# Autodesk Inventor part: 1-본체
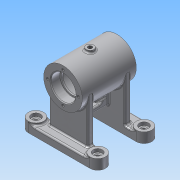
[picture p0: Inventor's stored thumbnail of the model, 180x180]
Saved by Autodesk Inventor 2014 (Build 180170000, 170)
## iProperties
Created: 2015-11
Part Number: 1-본체
Material: 알루미늄 6061
Document SubType Name: Modeling
Designer: 03
Mass: 359.022 g
Surface Area: 459.449 cm^2
Volume: 132.48 cm^3
Density: 2.71 g/cm^3
Appearance: 알루미늄 - 평지
Author: 03
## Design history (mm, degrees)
sketch "스케치1"
  geometry: L1 (-40, 40)-(40, 40); L2 (40, 40)-(40, 20); L3 (40, 20)-(-40, 20); L4 (-40, 20)-(-40, 40); L5 (0, 0)-(-40, 0); L6 (-40, -40)-(40, -40); L7 (40, -40)-(40, -20); L8 (40, -20)-(-40, -20); L9 (-40, -20)-(-40, -40); A1 r 10 centre (40, 30) between (40, 20) and (40, 40); A2 r 10 centre (-40, 30) between (-40, 40) and (-40, 20); A3 r 10 centre (40, -30) between (40, -40) and (40, -20); A4 r 10 centre (-40, -30) between (-40, -20) and (-40, -40); 2 further points
  constraints: 18 end point, 8 point on circle, 7 symmetric about line, 4 centre point, 3 midpoint, 2 parallel, 2 perpendicular, 1 horizontal, 1 vertical alignment, 2 other
  dimensions: "d0" = 20 distance of L1.end L2.end; "d1" = 80 distance of L1.start L1.end; "d2" = 40 distance from line of L5.start L1; "d3" = 40 distance of L5.start L5.end
extrude "돌출1" new body sketch "스케치1" distance "d4" = 10; taper "d5" = 0 deg
sketch "스케치2"
  geometry: L1 (40, 40)-(-40, 40) reference; L2 (-40, 20)-(40, 20) reference; A1 r 10 centre (40, -30) between (40, -40) and (40, -20) reference; A2 r 10 centre (-40, -30) between (-40, -20) and (-40, -40) reference; A3 r 10 centre (-40, 30) between (-40, 40) and (-40, 20) reference; A4 r 10 centre (40, 30) between (40, 20) and (40, 40) reference; 5 further points
  constraints: 4 coincident, 4 vertical alignment, 8 other
extrude "돌출2" join sketch "스케치2" distance "d6" = 3; taper "d7" = 0 deg
hole "구멍1" diameter "d10" = 6; stored, may be unused: countersink angle "d14" = 90 deg, drill point angle "d16" = 118 deg; dims "d8" = 10, "d9" = 10, "d11" = 6, "d12" = 12, "d13" = 4, "d15" = 8
hole "구멍2" diameter "d19" = 6; stored, may be unused: countersink angle "d23" = 90 deg, drill point angle "d25" = 118 deg; dims "d17" = 10, "d18" = 10, "d20" = 6, "d21" = 12, "d22" = 4, "d24" = 8
hole "구멍3" diameter "d28" = 6; stored, may be unused: countersink angle "d32" = 90 deg, drill point angle "d34" = 118 deg; dims "d26" = 10, "d27" = 10, "d29" = 6, "d30" = 12, "d31" = 4, "d33" = 8
hole "구멍4" diameter "d37" = 6; stored, may be unused: countersink angle "d41" = 90 deg, drill point angle "d43" = 118 deg; dims "d35" = 10, "d36" = 10, "d38" = 6, "d39" = 12, "d40" = 4, "d42" = 8
sketch "스케치5"
  geometry: L1 (-35, 68)-(35, 68); L2 (-35, 93)-(-35, 85); L3 (-34, 84)-(-23.3, 84); L4 (-23, 83.7)-(-23, 82); L5 (-23, 82)-(-21, 82); L6 (-21, 82)-(-21, 86); L7 (-18, 89)-(18, 89); L8 (21, 86)-(21, 82); L9 (21, 82)-(23, 82); L10 (23, 82)-(23, 83.7); L11 (23.3, 84)-(34, 84); L12 (35, 85)-(35, 93); L13 (35, 93)-(-35, 93); L14 (-35, 85)-(-34, 84); L15 (34, 84)-(35, 85); A1 r 0.3 centre (-23.3, 83.7) between (-23, 83.7) and (-23.3, 84); A2 r 0.3 centre (23.3, 83.7) between (23.3, 84) and (23, 83.7); A3 r 3 centre (18, 86) between (21, 86) and (18, 89); A4 r 3 centre (-18, 86) between (-18, 89) and (-21, 86); 9 further points
  constraints: 30 end point, 13 point on line, 9 parallel, 8 point on circle, 8 tangent, 4 centre point, 2 collinear, 2 midpoint, 2 perpendicular, 2 vertical alignment, 1 equal radius, 1 horizontal
  dimensions: "d66" = 68 vertical distance of point (0, 0) L1.end; "d67" = 32 diameter of L3 L1; "d68" = 28 diameter of L5 L1; "d69" = 28 diameter of L9 L1; "d70" = 32 diameter of L11 L1; "d71" = 42 diameter of L7 L1; "d72" = 42 distance of point (-21, 89) point (21, 89); "d73" = 12 distance of point (23, 84) point (35, 84); "d74" = 12 distance of point (-35, 84) point (-23, 84); "d75" = 70 distance of L12.end L2.start; "d76" = 50 diameter of L13 L1; "d78" = 0.3 radius of A1; "d79" = 0.3 radius of A2; "d80" = 3 radius of A3; "d81" = 1 distance of L2.end point (-35, 84); "d82" = 1 distance of L3.start point (-35, 84) (= d81); "d83" = 1 distance of L11.end point (35, 84) (= d81); "d84" = 1 distance of L12.start point (35, 84) (= d83)
revolve "회전2" sketch "스케치5" stored, may be unused: angle "d77" = 90 deg
sketch "스케치4"
  geometry: L1 (40, -20)-(-40, -20) reference; L2 (-40, 40)-(40, 40) reference; L3 (40, 20)-(-40, 20) reference; L4 (-25, -20)-(25, -20); L5 (25, -20)-(25, -28); L6 (25, -28)-(-25, -28); L7 (-25, -28)-(-25, -20); L8 (-25, 20)-(25, 20); L9 (25, 20)-(25, 28); L10 (25, 28)-(-25, 28); L11 (-25, 28)-(-25, 20); C1 r 3 at (40, 30) reference; C2 r 3 at (-40, 30) reference; A1 r 10 centre (40, 30) between (40, 20) and (40, 40) reference; A2 r 10 centre (-40, 30) between (-40, 40) and (-40, 20) reference; 3 further points
  constraints: 16 end point, 4 parallel, 2 horizontal, 2 midpoint, 2 perpendicular, 2 point on line, 2 vertical alignment
  dimensions: "d62" = 8 distance of L8.end L9.end; "d63" = 8 distance of L4.end L5.end; "d64" = 50 distance of L5.end L6.end; "d65" = 50 distance of L9.end L10.end
extrude "돌출3" join sketch "스케치4" stored distance "d85" = 3; taper "d86" = 0 deg
sketch "스케치6"
  geometry: L1 (-35, 43)-(35, 43) reference; L2 (-20, 45.5)-(20, 45.5); L3 (20, 45.5)-(20, 23); L4 (20, 23)-(-20, 23); L5 (-20, 23)-(-20, 45.5); L6 (-20, 10)-(-20, 68) reference; L7 (20, 10)-(20, 68) reference; L8 (-8, 33)-(8, 33); L9 (-8, 29.5)-(8, 29.5); L10 (8, 36.5)-(-8, 36.5); A1 r 3.5 centre (-8, 33) between (-8, 36.5) and (-8, 29.5); A2 r 3.5 centre (8, 33) between (8, 29.5) and (8, 36.5); 2 further points
  constraints: 16 end point, 4 parallel, 4 point on circle, 4 tangent, 2 centre point, 2 collinear, 1 horizontal, 1 midpoint, 1 perpendicular, 1 vertical alignment
  dimensions: "d87" = 20 distance between parallel lines of L4 L1; "d88" = 23 dimension on A2 A1; "d89" = 3.5 radius of A2; "d90" = 33 distance from line of point (0, 0) L8; "d91" = 2.5 distance between parallel lines of L1 L2
extrude "돌출4" join sketch "스케치6" stored distance "d92" = 8; taper "d93" = 0 deg
node "작업 평면1"
sketch "스케치7"
  geometry: C1 r 5 at (0, 0); 1 further point
  constraints: 1 centre point, 1 coincident
  dimensions: "d95" = 10 diameter of C1
extrude "돌출5" join sketch "스케치7" stored distance "d96" = 8; taper "d97" = 0 deg
hole "구멍5" diameter "d100" = 5.188; stored, may be unused: countersink angle "d104" = 90 deg, drill point angle "d106" = 118 deg; dims "d98" = 10, "d99" = 10, "d101" = 6, "d102" = 12, "d103" = 4, "d105" = 8
fillet "모깎기1" dims "d107" = 2
node "작업 평면2"
sketch "스케치8"
  geometry: L1 (35, 25)-(-35, 25) reference; L2 (-35, 25)-(-35, -25) reference; 2 further points
  constraints: 1 other
  dimensions: "d108" = 25 distance from line of L1 point (0, 0); "d109" = 35 distance from line of point (0, 0) L2
feature "엠보싱1" sketch "스케치8" dims "d0" = 20, "d1" = 80, "d2" = 40, "d3" = 40, "d110" = 0.5, "d111" = 0
sketch "스케치9"
  geometry: L1 (0, 68)-(0, 47); L2 (0, 68)-(-14, 43.751); L3 (-14, 43.751)-(-19.196, 46.751); L4 (-19.196, 46.751)-(-16.696, 51.081); L5 (-16.696, 51.081)-(-11.5, 48.081); 1 further point
  constraints: 10 end point, 3 perpendicular, 1 point on line, 1 vertical, 1 vertical alignment, 1 other
  dimensions: "d112" = 30 deg angle of L1 L2; "d113" = 12 diameter of L4 L2; "d114" = 28 distance from line of L1.start L3; "d115" = 5 distance of L3.end L4.end
revolve "회전3" sketch "스케치9" stored, may be unused: angle "d116" = 90 deg
hole "구멍6" diameter "d119" = 5.188; stored, may be unused: countersink angle "d123" = 90 deg, drill point angle "d125" = 118 deg; dims "d117" = 10, "d118" = 10, "d120" = 6, "d121" = 12, "d122" = 4, "d124" = 8
fillet "모깎기2" dims "d126" = 2
sketch "스케치10"
  geometry: C1 r 25 at (0, 0) reference; 5 further points
  constraints: 1 vertical alignment, 5 other
  dimensions: "d127" = 20 distance of C1.centre point (0, 20); "d130" = 360 deg dimension on C1.centre point (0, 20) (derived)
hole "구멍7" sketch "스케치10" at (0, 20), (-20, 0), (0, -20), (20, 0) diameter "d132" = 3.242; stored, may be unused: countersink angle "d136" = 90 deg, drill point angle "d138" = 118 deg; dims "d133" = 8, "d134" = 12, "d135" = 4, "d137" = 10
fillet "모깎기3" dims "d139" = 0.3
chamfer "모따기1" distance "d140" = 1; stored, may be unused: second distance "d141" = 2, angle "d142" = 45 deg
fillet "모깎기4" dims "d143" = 2
fillet "모깎기5" dims "d144" = 2
node "솔리드1"
mirror "대칭1"
node "투영된 루프1"
node "투영된 루프2"
other parameters: "d94" = 96
